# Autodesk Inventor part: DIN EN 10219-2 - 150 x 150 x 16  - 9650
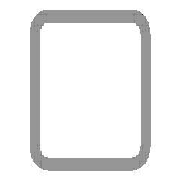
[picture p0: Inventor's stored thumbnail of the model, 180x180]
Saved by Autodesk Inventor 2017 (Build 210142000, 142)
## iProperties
IsCustomPart: 1
Created: 2017-11
Part Number: DIN EN 10219-2 - 150 x 150 x 16  - 9650
Material: Steel, Mild
Description: Cold formed welded structural hollow sections of non-alloy and fine grain structural steel
Document SubType Name: Modeling
Standard: DIN
Designer: iusti
Standard Revision: 2006-07
Standards Organization: DIN
Language: en-US
Size Designation: 150 x 150 x 16
Categories: <MemberInstance><Categories><Category DisplayName="Structural Shapes" InternalName="089c4875-fa83-4c05-b084-43b9cc11f5ed" Mnemonic="GRDR"><CategoryParameter Dis
Stock Number: 150 x 150 x 16
Density: 7.85 g/cm^3
Appearance: Semi-Polished
Mass: 557615 g
Surface Area: 89003.7 cm^2
Volume: 71033.8 cm^3
_CCFamilyMember: 76
_CCFamilyDisplayName: DIN EN 10219-2 (Square Hollow Section - Cold Formed) - Cold formed welded structural hollow sections of non-alloy and fine grain structural steel
_FrameMemberDoc: Frame Member File
_Version: 15.0.0
_GetPNFromCC: 1
G_L: 9650.000 mm
G_W: 150.000 mm
G_H: 150.000 mm
+B9E1DA22-D309-4BBF-9627-4CE74C33B13E+CUTDETAIL1: Cut
+2FA9747E-09CC-4283-B5AE-DE9A0485B1EC+CUTDETAIL2: Cut
+00569EB8-A9A7-487F-AD20-8A8F135713C5+CUTDETAIL3: Miter 45.00 deg
+1BFDA885-F50F-46B1-BDA8-57B8AE23BE4C+CUTDETAIL4: Miter 45.00 deg
Author: iusti
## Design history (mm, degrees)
node "Start plane"
node "End plane"
sketch "Sketch"
  geometry: L1 (-75, -27)-(-75, 27); L2 (-27, 75)-(27, 75); L3 (75, 27)-(75, -27); L4 (27, -75)-(-27, -75); L5 (-27, 59)-(27, 59); L6 (59, 27)-(59, -27); L7 (27, -59)-(-27, -59); L8 (-59, -27)-(-59, 27); L9 (0, 118.918)-(0, -118.918) reference; L10 (-118.918, 0)-(118.918, 0) reference; A1 r 48 centre (-27, -27) between (-75, -27) and (-27, -75); A2 r 48 centre (-27, 27) between (-27, 75) and (-75, 27); A3 r 48 centre (27, 27) between (75, 27) and (27, 75); A4 r 48 centre (27, -27) between (27, -75) and (75, -27); A5 r 32 centre (-27, 27) between (-27, 59) and (-59, 27); A6 r 32 centre (27, 27) between (59, 27) and (27, 59); A7 r 32 centre (27, -27) between (27, -59) and (59, -27); A8 r 32 centre (-27, -27) between (-59, -27) and (-27, -59)
  constraints: 16 end point, 16 point on circle, 8 centre point, 8 tangent, 4 parallel, 3 equal radius, 2 perpendicular, 7 other
  dimensions: "d7" = 48 radius of A1 (= G_IR); "d10" = 150 distance between parallel lines of L2 L4 (= G_H); "d11" = 150 distance between parallel lines of L1 L3 (= G_W); "d12" = 16 distance between parallel lines of L3 L6 (= G_T); "d15" = 75 distance between parallel lines of L2 L10 (= 0.5 x d10); "d16" = 75 distance between parallel lines of L9 L3 (= 0.5 x d11)
extrude "Body" new body sketch "Sketch" stored distance "d3" = 9650 (= G_L); taper "d4" = 0 deg
node "Driven Length"
  sketch "Sketch3"
    geometry: L1 (0, 0)-(10, 0) reference
    constraints: 2 end point, 1 horizontal
  workplane "Work Plane3"
  sketch "Sketch4"
    geometry: L1 (-2, -75)-(12, -75) reference; L2 (-2, 9575)-(12, 9575) reference
    dimensions: "d18" = 9650 distance between parallel lines of L1 L2 (derived)
workplane "Work Plane4"
split "Split1"
workplane "Work Plane5"
split "Split2"
workplane "Work Plane6"
split "Split3"
workplane "Work Plane7"
split "Split4"
body "Solid1"
other parameters: "G_W" = 150 [user parameter; used in 1 equation term], "G_H" = 150 [user parameter; used in 1 equation term], "G_T" = 16 [user parameter; used in 1 equation term], "G_IR" = 48 [user parameter; used in 1 equation term], "G_L" = 9650 (= d18) [user parameter; used in 1 equation term], "G_OFFSET_START" = 75 [user parameter; used in 1 equation term], "G_OFFSET_END" = 75 [user parameter; used in 1 equation term], "d13" = -75 (= -G_OFFSET_START), "d14" = 9575 (= G_OFFSET_END + B_L), "d17" = 90 deg
